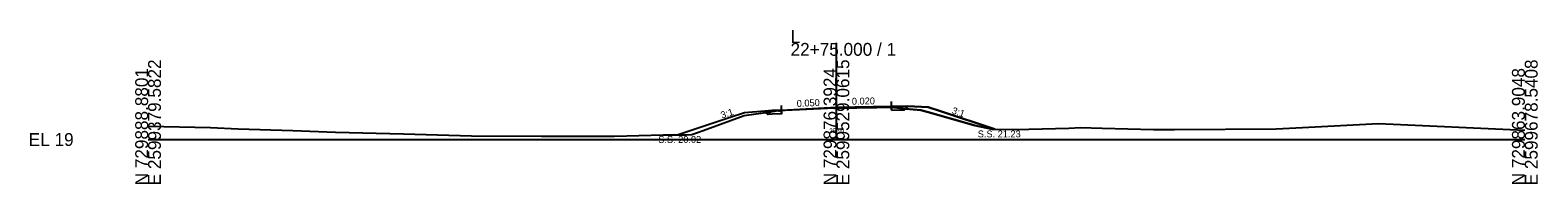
# Model space of a CAD drawing. Extents: x -26 to 3303, y -10 to 9555.
# Drawn here: x 1974.3 to 2302.8, y 5490.3 to 5523.9 of the extents above; entities that cross this region are included whole.
import ezdxf

# ---------------------------------------------------------------- set-up
doc = ezdxf.new("R2010")
doc.units = 0
for name, color, linetype in [('Exist Cross Section Cell', 7, 'Continuous'), ('Exist XS Center Line Elevation Label', 7, 'Continuous'), ('Exist XS Ground Line', 7, 'Continuous'), ('Prop XS Dump Level', 7, 'Continuous'), ('Prop XS Earthwork Shape', 7, 'Continuous'), ('Prop XS EOT Tick Mark', 7, 'Continuous'), ('Prop XS Finish Grade', 7, 'Continuous'), ('Prop XS Finish Grade Earthwork', 7, 'Continuous'), ('Prop XS Finish Grade Paved Shoulder', 7, 'Continuous'), ('Prop XS Finish Grade Pavement', 7, 'Continuous'), ('Prop XS Pvmt Edge Slope', 7, 'Continuous'), ('Prop XS SE Text', 7, 'Continuous'), ('Prop XS Side Slope Text', 7, 'Continuous'), ('Prop XS SS Elevation Text', 7, 'Continuous'), ('Prop XS Subgrade Earthwork', 7, 'Continuous')]:
    doc.layers.add(name, color=color, linetype=linetype)

msp = doc.modelspace()

# ---------------------------------------------------------------- linework, layer by layer
at = {"layer": 'Exist Cross Section Cell'}
for p, q in [((2150, 5500), (2150, 5521.09)), ((2000, 5500), (2150, 5500)), ((2150, 5500), (2300, 5500))]:
    msp.add_line(p, q, dxfattribs=at)
at = {"layer": 'Exist XS Ground Line'}
msp.add_lwpolyline([(2000, 5502.95), (2013.6, 5502.62), (2019.61, 5502.34), (2031.57, 5502), (2040.86, 5501.64), (2055.67, 5501.23), (2070.48, 5500.83), (2085.75, 5500.7), (2093.57, 5500.74), (2101.67, 5500.73), (2112.23, 5500.99), (2117.32, 5501.04), (2118.48, 5501.13), (2120.95, 5501.97), (2129.88, 5505.22), (2136.52, 5506.21), (2137.31, 5506.32), (2144.98, 5506.7), (2149.57, 5506.91), (2150, 5506.91), (2154.48, 5506.95), (2156.94, 5506.97), (2158.81, 5506.99), (2161.99, 5507.03), (2164.3, 5506.79), (2168.4, 5506.41), (2170.81, 5505.75), (2180.15, 5503.09), (2183.9, 5502.24), (2189, 5502.16), (2200.66, 5502.47), (2203.19, 5502.62), (2207.92, 5502.49), (2219.1, 5502.21), (2223.68, 5502.17), (2245.83, 5502.31), (2251.58, 5502.66), (2268.1, 5503.51), (2300, 5502.07)], dxfattribs=at)
at = {"layer": 'Prop XS Dump Level'}
for p, q in [((2138, 5506.43), (2150, 5507.03)), ((2150, 5507.03), (2162, 5507.27))]:
    msp.add_line(p, q, dxfattribs=at)
at = {"layer": 'Prop XS Earthwork Shape'}
for points in [[(2138, 5505.6), (2136, 5505.5), (2135.12, 5505.46), (2134.64, 5505.93), (2136.52, 5506.21), (2137.31, 5506.32), (2138, 5506.36)], [(2134.64, 5505.93), (2136.52, 5506.21), (2137.31, 5506.32), (2138, 5506.36), (2138, 5505.6), (2136, 5505.5), (2135.12, 5505.46)], [(2161.99, 5506.44), (2162, 5506.44), (2164, 5506.48), (2164.82, 5506.5), (2165.04, 5506.72), (2164.3, 5506.79), (2161.99, 5507.03)], [(2161.99, 5506.44), (2162, 5506.44), (2164, 5506.48), (2164.82, 5506.5), (2165.04, 5506.72), (2164.3, 5506.79), (2161.99, 5507.03)], [(2180.15, 5503.09), (2183.9, 5502.24), (2184.52, 5502.23), (2172.67, 5506.18), (2170, 5507.07), (2165.57, 5507.25), (2165.04, 5506.72), (2168.4, 5506.41), (2170.81, 5505.75)], [(2172.67, 5506.18), (2184.52, 5502.23), (2183.9, 5502.24), (2180.15, 5503.09), (2170.81, 5505.75), (2168.4, 5506.41), (2165.04, 5506.72), (2165.57, 5507.25), (2170, 5507.07)], [(2134.38, 5506.2), (2130, 5505.85), (2126.81, 5504.79), (2115.51, 5501.02), (2117.32, 5501.04), (2118.48, 5501.13), (2120.95, 5501.97), (2129.88, 5505.22), (2134.64, 5505.93)], [(2130, 5505.85), (2126.81, 5504.79), (2115.51, 5501.02), (2117.32, 5501.04), (2118.48, 5501.13), (2120.95, 5501.97), (2129.88, 5505.22), (2134.64, 5505.93), (2134.38, 5506.2)]]:
    msp.add_lwpolyline(points, close=True, dxfattribs=at)
at = {"layer": 'Prop XS EOT Tick Mark'}
for p, q in [((2138, 5506.43), (2138, 5507.43)), ((2162, 5507.27), (2162, 5508.27))]:
    msp.add_line(p, q, dxfattribs=at)
at = {"layer": 'Prop XS Finish Grade'}
for p, q in [((2136, 5506.33), (2134.38, 5506.2)), ((2164, 5507.31), (2165.57, 5507.25))]:
    msp.add_line(p, q, dxfattribs=at)
at = {"layer": 'Prop XS Finish Grade Earthwork'}
for p, q in [((2165.57, 5507.25), (2170, 5507.07)), ((2170, 5507.07), (2172.67, 5506.18)), ((2126.81, 5504.79), (2115.51, 5501.02)), ((2130, 5505.85), (2126.81, 5504.79)), ((2134.38, 5506.2), (2130, 5505.85)), ((2172.67, 5506.18), (2184.52, 5502.23))]:
    msp.add_line(p, q, dxfattribs=at)
at = {"layer": 'Prop XS Finish Grade Paved Shoulder'}
for p, q in [((2138, 5506.43), (2136, 5506.33)), ((2162, 5507.27), (2164, 5507.31))]:
    msp.add_line(p, q, dxfattribs=at)
at = {"layer": 'Prop XS Finish Grade Pavement'}
for p, q in [((2138, 5506.43), (2150, 5507.03)), ((2150, 5507.03), (2162, 5507.27))]:
    msp.add_line(p, q, dxfattribs=at)
at = {"layer": 'Prop XS Pvmt Edge Slope'}
for p, q in [((2136, 5506.33), (2135.12, 5505.46)), ((2164, 5507.31), (2164.82, 5506.5)), ((2164.82, 5506.5), (2165.57, 5507.25)), ((2135.12, 5505.46), (2134.38, 5506.2))]:
    msp.add_line(p, q, dxfattribs=at)
at = {"layer": 'Prop XS Subgrade Earthwork'}
for p, q in [((2138, 5505.6), (2138, 5506.36)), ((2161.99, 5506.44), (2161.99, 5507.03)), ((2161.99, 5506.44), (2162, 5506.44)), ((2162, 5506.44), (2164, 5506.48)), ((2164, 5506.48), (2164.82, 5506.5)), ((2164.82, 5506.5), (2165.57, 5507.25)), ((2135.12, 5505.46), (2134.38, 5506.2)), ((2136, 5505.5), (2135.12, 5505.46)), ((2138, 5505.6), (2136, 5505.5))]:
    msp.add_line(p, q, dxfattribs=at)

# ---------------------------------------------------------------- texts
at = {"layer": 'Exist Cross Section Cell'}
for s, p in [('L', (2140, 5521.09)), ('22+75.000 / 1', (2140, 5518.29)), ('EL 19', (1974, 5498.6))]:
    msp.add_text(s, height=2.8, dxfattribs=at).set_placement(p)
for s, p in [('E 2599379.5822', (2002.8, 5490)), ('E 2599529.0615', (2152.8, 5490)), ('E 2599678.5408', (2302.8, 5490)), ('N 729888.8801', (2000, 5490)), ('N 729876.3924', (2150, 5490)), ('N 729863.9048', (2300, 5490))]:
    msp.add_text(s, height=2.8, rotation=90, dxfattribs=at).set_placement(p)
at = {"layer": 'Exist XS Center Line Elevation Label'}
msp.add_text('25.91', height=1, dxfattribs=at).set_placement((2148.43, 5501.41))
at = {"layer": 'Prop XS Dump Level'}
for s, height, p in [('Eop', 0.3, (2137.31, 5506.02)), ('Eop', 0.3, (2161.99, 5506.73)), ('Case1', 0.04, (2170, 5507.03)), ('Case1', 0.04, (2130, 5505.81))]:
    msp.add_text(s, height=height, dxfattribs=at).set_placement(p)
at = {"layer": 'Prop XS SE Text'}
for s, rotation, p in [('0.050', 2.8624, (2141.38, 5507.1)), ('0.020', 1.1458, (2153.38, 5507.6))]:
    msp.add_text(s, height=1.5, rotation=rotation, dxfattribs=at).set_placement(p)
at = {"layer": 'Prop XS Side Slope Text'}
for rotation, p in [(18.4349, (2125.07, 5504.55)), (341.5651, (2175.03, 5505.71))]:
    msp.add_text('3:1', height=1.5, rotation=rotation, dxfattribs=at).set_placement(p)
at = {"layer": 'Prop XS SS Elevation Text'}
for s, p in [('S.S. 20.02', (2111.16, 5499.26)), ('S.S. 21.23', (2180.79, 5500.47))]:
    msp.add_text(s, height=1.5, dxfattribs=at).set_placement(p)

doc.saveas('drawing.dxf')
